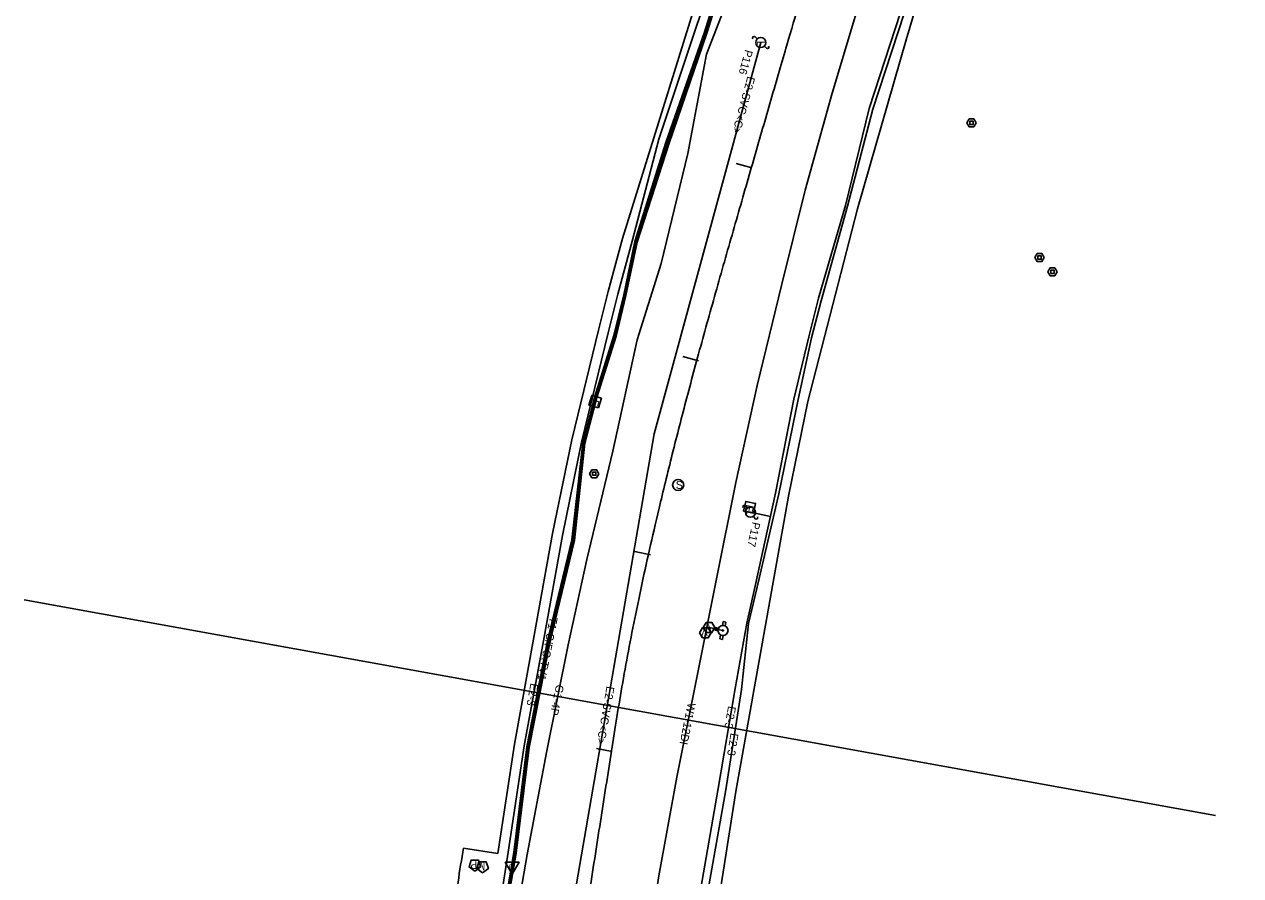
# Model space of a CAD drawing. Extents: x 1991878 to 2008544, y 770238 to 1141211.
# Drawn here: x 2007275 to 2007882, y 1138111 to 1138537 of the extents above; entities that cross this region are included whole.
import ezdxf

# ---------------------------------------------------------------- set-up
doc = ezdxf.new("R2010")
doc.units = 0
for name, color, linetype in [('RD_EX_SU_Elec', 7, 'Continuous'), ('RD_EX_SU_Gas', 7, 'Continuous'), ('RD_EX_SU_H2O', 7, 'Continuous'), ('RD_EX_SU_Misc', 7, 'Continuous'), ('RD_EX_SU_Pole', 7, 'Continuous'), ('RD_EX_SU_Sewer', 7, 'Continuous'), ('RD_EX_SU_SwpLmt', 7, 'Continuous'), ('RD_EX_SU_Telecom', 7, 'Continuous'), ('RD_EX_SU_TX_Elec', 7, 'Continuous'), ('RD_EX_SU_TX_Gas', 7, 'Continuous'), ('RD_EX_SU_TX_H2O', 7, 'Continuous'), ('RD_EX_SU_TX_Pole', 7, 'Continuous'), ('RD_EX_SU_TX_Telecom', 7, 'Continuous'), ('RD_HC_Cl', 7, 'Continuous')]:
    doc.layers.add(name, color=color, linetype=linetype)

msp = doc.modelspace()

# ---------------------------------------------------------------- linework, layer by layer
at = {"layer": 'RD_EX_SU_Elec'}
msp.add_line((2007637.43, 1138292.75), (2007647.39, 1138290.57), dxfattribs=at)
for points in [[(2007706.83, 1138822.62), (2007704.76, 1138818.43), (2007686.36, 1138768.29), (2007670.15, 1138718.93), (2007655.58, 1138671.59), (2007638.85, 1138621.77), (2007624.34, 1138576.36), (2007610.08, 1138534.72), (2007591.61, 1138479.18), (2007578.34, 1138428.3), (2007571.2, 1138401.76), (2007566.3, 1138382.49), (2007552.98, 1138327.8), (2007543.47, 1138281.15), (2007534.02, 1138228.49), (2007524.41, 1138175.98), (2007516.35, 1138122.86), (2007508.64, 1138073.54), (2007501.32, 1138025.38), (2007493.66, 1137973), (2007490.32, 1137950.52), (2007490.01, 1137946.93)], [(2007712.49, 1138542.43), (2007696.83, 1138494.53), (2007685.02, 1138446.06), (2007671.46, 1138399.73), (2007666.58, 1138380.33), (2007659.17, 1138349.31), (2007649.94, 1138302.21), (2007639.62, 1138255.08), (2007635.71, 1138237.27), (2007629.85, 1138204.64), (2007621.3, 1138154.75), (2007612.68, 1138104.93), (2007606.14, 1138053.84), (2007599.77, 1138007.06), (2007596.84, 1137986.3), (2007591.59, 1137955.78), (2007589.06, 1137927.38), (2007586.07, 1137909.2), (2007586.26, 1137894.25), (2007587.74, 1137889.07)], [(2007714.26, 1138542.06), (2007698.61, 1138494.14), (2007686.02, 1138445.77), (2007672.82, 1138398.47), (2007667.98, 1138379.97), (2007661.22, 1138349.15), (2007651.59, 1138301.88), (2007640.57, 1138254.66), (2007636.43, 1138237.15), (2007632.95, 1138204.15), (2007625.16, 1138154.04), (2007616.3, 1138104.21), (2007609.78, 1138053.19), (2007601.94, 1138006.51), (2007599.37, 1137985.94), (2007593.19, 1137955.57), (2007590.35, 1137927.51), (2007587.53, 1137909.08), (2007587.7, 1137893.93), (2007587.74, 1137889.07)], [(2007538.15, 1137074.35), (2007519.64, 1137210), (2007505.46, 1137340.1), (2007504.07, 1137566.44), (2007504, 1137727.5), (2007520.49, 1137915.5), (2007511.47, 1137939.68), (2007504.53, 1137943.1), (2007494.61, 1137946.88), (2007490.01, 1137946.93), (2007494.71, 1137947.7), (2007504.89, 1137945.37), (2007508.98, 1137946.44), (2007510.73, 1137950.05), (2007517.78, 1137999.33), (2007545.65, 1138079.09), (2007589.39, 1138331.96), (2007642.59, 1138527.53)]]:
    msp.add_lwpolyline(points, dxfattribs=at)
msp.add_lwpolyline([(2007638.93, 1138292.25), (2007639.98, 1138297.14), (2007635.09, 1138298.19), (2007634.04, 1138293.3)], close=True, dxfattribs=at)
at = {"layer": 'RD_EX_SU_Gas'}
msp.add_lwpolyline([(2007634.42, 1138570.59), (2007615.51, 1138521.62), (2007606.1, 1138472.02), (2007592.8, 1138417.02), (2007580.86, 1138378.9), (2007568.59, 1138323.23), (2007555.66, 1138269.15), (2007546.41, 1138226.42), (2007535.61, 1138173.44), (2007525.93, 1138121.66), (2007517.31, 1138072.53), (2007510.66, 1138020.37), (2007506.64, 1137971.23), (2007506.3, 1137957.32), (2007504.57, 1137918.34), (2007499.45, 1137870.97), (2007496.13, 1137817.71), (2007491.79, 1137765.75), (2007491.75, 1137759.97), (2007489.77, 1137717.72), (2007489.6, 1137706.9), (2007487.5, 1137663.95)], dxfattribs=at)
at = {"layer": 'RD_EX_SU_H2O'}
for p, q in [((2007623.89, 1138238.11), (2007623.49, 1138236.12)), ((2007625.13, 1138237.87), (2007623.89, 1138238.11)), ((2007624.74, 1138235.92), (2007625.13, 1138237.87)), ((2007619.89, 1138235.08), (2007619.64, 1138233.84)), ((2007619.64, 1138233.84), (2007621.21, 1138233.53)), ((2007621.49, 1138234.76), (2007619.89, 1138235.08)), ((2007622.55, 1138231.39), (2007622.17, 1138229.46)), ((2007622.17, 1138229.46), (2007623.41, 1138229.22)), ((2007623.41, 1138229.22), (2007623.78, 1138231.09))]:
    msp.add_line(p, q, dxfattribs=at)
for points in [[(2007548.97, 1137663.53), (2007550.1, 1137712.27), (2007552.81, 1137762.67), (2007556.77, 1137812.3), (2007561.23, 1137862.39), (2007566.19, 1137911.98), (2007570.32, 1137961.89), (2007576.38, 1138011.99), (2007581, 1138044.96), (2007583.81, 1138061.61), (2007586.91, 1138079.97), (2007591.59, 1138111.01), (2007600.73, 1138160.37), (2007610.7, 1138210.15), (2007620.53, 1138259.51), (2007630.19, 1138307.66), (2007640.83, 1138356.11), (2007652.92, 1138406.01), (2007664.84, 1138453.65), (2007678.31, 1138502.25), (2007692.96, 1138551.24)], [(2007615.71, 1138235.31), (2007616.04, 1138235.25), (2007622.84, 1138233.72), (2007623.73, 1138233.61)]]:
    msp.add_lwpolyline(points, dxfattribs=at)
for points in [[(2007613.88, 1138235.11), (2007615.32, 1138232.61), (2007618.21, 1138232.61), (2007619.65, 1138235.11), (2007618.21, 1138237.61), (2007615.32, 1138237.61)], [(2007612.06, 1138232.54), (2007613.5, 1138230.04), (2007616.39, 1138230.04), (2007617.83, 1138232.54), (2007616.39, 1138235.04), (2007613.5, 1138235.04)], [(2007499.7, 1138113.33), (2007502.6, 1138115.44), (2007501.5, 1138118.85), (2007497.91, 1138118.85), (2007496.8, 1138115.44)], [(2007503.56, 1138112.54), (2007506.46, 1138114.65), (2007505.35, 1138118.06), (2007501.77, 1138118.06), (2007500.66, 1138114.65)]]:
    msp.add_lwpolyline(points, close=True, dxfattribs=at)
for radius in [2.52, 0.315]:
    msp.add_circle((2007623.73, 1138233.61), radius, dxfattribs=at)
for start, end in [(153.00647, 181.97371), (242.09965, 271.07597), (66.44593, 95.42225)]:
    msp.add_arc((2007623.73, 1138233.61), 2.52, start, end, dxfattribs=at)
at = {"layer": 'RD_EX_SU_Misc'}
msp.add_lwpolyline([(2007518.34, 1138111.79), (2007521.81, 1138117.79), (2007514.88, 1138117.79)], close=True, dxfattribs=at)
at = {"layer": 'RD_EX_SU_Pole'}
for p, q in [((2007639.76, 1138530.36), (2007640.83, 1138529.3)), ((2007644.36, 1138525.77), (2007645.42, 1138524.7)), ((2007635.06, 1138295.96), (2007635.95, 1138294.76)), ((2007638.92, 1138290.73), (2007639.81, 1138289.53))]:
    msp.add_line(p, q, dxfattribs=at)
for centre in [(2007642.59, 1138527.53), (2007637.43, 1138292.75)]:
    msp.add_circle(centre, 2.5, dxfattribs=at)
for centre, start, end in [((2007639.23, 1138529.83), 45, 225), ((2007645.95, 1138525.23), 225, 45), ((2007634.45, 1138295.52), 36.44594, 216.44594), ((2007640.41, 1138289.97), 216.44594, 36.44594)]:
    msp.add_arc(centre, 0.75, start, end, dxfattribs=at)
at = {"layer": 'RD_EX_SU_Sewer'}
for points in [[(2007750.24, 1138487.35), (2007749.09, 1138489.35), (2007746.78, 1138489.35), (2007745.62, 1138487.35), (2007746.78, 1138485.35), (2007749.09, 1138485.35)], [(2007748.75, 1138488.17), (2007747.12, 1138488.17), (2007747.11, 1138486.53), (2007748.75, 1138486.53)], [(2007784.25, 1138420.03), (2007783.09, 1138422.03), (2007780.79, 1138422.03), (2007779.63, 1138420.03), (2007780.79, 1138418.03), (2007783.09, 1138418.03)], [(2007782.76, 1138420.84), (2007781.12, 1138420.84), (2007781.12, 1138419.21), (2007782.75, 1138419.21)], [(2007790.71, 1138412.91), (2007789.56, 1138414.9), (2007787.25, 1138414.9), (2007786.09, 1138412.91), (2007787.25, 1138410.91), (2007789.56, 1138410.91)], [(2007789.22, 1138413.72), (2007787.59, 1138413.72), (2007787.58, 1138412.09), (2007789.22, 1138412.09)], [(2007561.68, 1138312.01), (2007560.53, 1138314), (2007558.22, 1138314), (2007557.07, 1138312.01), (2007558.22, 1138310.01), (2007560.53, 1138310.01)], [(2007560.19, 1138312.82), (2007558.56, 1138312.82), (2007558.56, 1138311.19), (2007560.19, 1138311.19)]]:
    msp.add_lwpolyline(points, close=True, dxfattribs=at)
msp.add_circle((2007601.32, 1138306.39), 2.75, dxfattribs=at)
at = {"layer": 'RD_EX_SU_SwpLmt'}
msp.add_line((2007493.97, 1138124.93), (2007511.19, 1138122.18), dxfattribs=at)
for points in [[(2007702.34, 1138824.83), (2007634.1, 1138623.32), (2007619.59, 1138577.94), (2007573.51, 1138429.58), (2007566.36, 1138403.03), (2007561.45, 1138383.7), (2007548.1, 1138328.89), (2007538.56, 1138282.1), (2007529.1, 1138229.38), (2007519.48, 1138176.81), (2007511.19, 1138122.18)], [(2007715.28, 1138528.93), (2007690.88, 1138444.46), (2007666.14, 1138348.11), (2007656.52, 1138300.81), (2007630.12, 1138153.21), (2007606.92, 1138005.78), (2007592.75, 1137889.42)]]:
    msp.add_lwpolyline(points, dxfattribs=at)
for centre, radius, start, end in [((2009858.48, 1137910.13), 2230.75, 135.28907, 163.89519), ((2011139.83, 1137542.45), 3692.1, 170.92287, 171.45757)]:
    msp.add_arc(centre, radius, start, end, dxfattribs=at)
at = {"layer": 'RD_EX_SU_Telecom'}
for points in [[(2007628.19, 1138574.88), (2007615.18, 1138532.43), (2007595.94, 1138477.43), (2007580.19, 1138427.98), (2007574.61, 1138401.28), (2007569.71, 1138380.96), (2007560.17, 1138350.06), (2007554.14, 1138327.34), (2007548.86, 1138278.86), (2007536.67, 1138228.27), (2007526.24, 1138175.25), (2007519.69, 1138122.42), (2007511.37, 1138073.33), (2007502.97, 1138025.15), (2007497.48, 1137973.05), (2007494.94, 1137951.7), (2007491.53, 1137942.52), (2007485.03, 1137942.28)], [(2007627.59, 1138575.05), (2007614.5, 1138532.66), (2007595.23, 1138477.59), (2007579.66, 1138428.05), (2007574.13, 1138401.36), (2007569.16, 1138381.1), (2007559.54, 1138350.07), (2007553.63, 1138327.41), (2007548.17, 1138278.88), (2007536.03, 1138228.39), (2007525.7, 1138175.56), (2007519.11, 1138122.6), (2007510.79, 1138073.46), (2007502.45, 1138025.25), (2007496.97, 1137973.16), (2007494.45, 1137951.63), (2007491.1, 1137942.88), (2007488.59, 1137941.59)], [(2007628.91, 1138574.72), (2007615.65, 1138532.16), (2007596.75, 1138477.17), (2007580.91, 1138427.76), (2007575.16, 1138401.11), (2007570.39, 1138380.76), (2007560.7, 1138350.03), (2007554.69, 1138327.28), (2007549.53, 1138278.6), (2007537.28, 1138228.23), (2007526.8, 1138175.21), (2007520.39, 1138122.41), (2007511.93, 1138073.21), (2007503.52, 1138024.98), (2007498.02, 1137972.97), (2007495.54, 1137951.65), (2007491.98, 1137941.97), (2007488.59, 1137941.59)]]:
    msp.add_lwpolyline(points, dxfattribs=at)
msp.add_lwpolyline([(2007561.54, 1138344.95), (2007562.93, 1138349.75), (2007558.12, 1138351.14), (2007556.74, 1138346.34)], close=True, dxfattribs=at)
at = {"layer": 'RD_HC_Cl'}
for p, q in [((2007630.37, 1138467.05), (2007638.06, 1138464.86)), ((2007603.68, 1138370.52), (2007611.41, 1138368.47)), ((2007579.7, 1138273.11), (2007587.51, 1138271.38)), ((2007274.54, 1138248.89), (2007869.86, 1138141.15)), ((2007560.49, 1138174.58), (2007568.38, 1138173.24))]:
    msp.add_line(p, q, dxfattribs=at)
msp.add_open_spline([(2008468.44, 1139784.65), (2008330.54, 1139636.27), (2008112.04, 1139402.61), (2008010.65, 1139269.99), (2007954.96, 1139181.47), (2007845.36, 1139006.33), (2007807.05, 1138915.36), (2007714.1, 1138721), (2007657.93, 1138535.69), (2007584.82, 1138278.81), (2007557.24, 1138105.93), (2007524.47, 1137887.62), (2007511.86, 1137606.6), (2007518.19, 1137380.97), (2007535.52, 1137158.14), (2007573, 1136960.76), (2007648.83, 1136694.4), (2007817.41, 1136298.79), (2008044.24, 1135795.68), (2008373.08, 1135014.28)], degree=2, dxfattribs=at)

# ---------------------------------------------------------------- texts
at = {"layer": 'RD_EX_SU_Elec'}
for s, rotation, p in [('E2-SVC<C>', 254.78251, (2007635.98, 1138510.85)), ('E', 257.9388, (2007635.31, 1138296.82))]:
    msp.add_text(s, height=4, rotation=rotation, dxfattribs=at).set_placement(p)
at = {"layer": 'RD_EX_SU_H2O'}
for s, p in [('V', (2007616.15, 1138234.42)), ('V', (2007617.97, 1138236.99)), ('P', (2007500.86, 1138118.26)), ('M', (2007504.93, 1138117.58))]:
    msp.add_text(s, height=3.75, rotation=180, dxfattribs=at).set_placement(p)
at = {"layer": 'RD_EX_SU_Misc'}
msp.add_text('U', height=2.4, rotation=180, dxfattribs=at).set_placement((2007519.1, 1138116.99))
at = {"layer": 'RD_EX_SU_Pole'}
for rotation, p in [(270, (2007640.66, 1138528.34)), (261.44594, (2007635.64, 1138293.83))]:
    msp.add_text('L', height=4, rotation=rotation, dxfattribs=at).set_placement(p)
at = {"layer": 'RD_EX_SU_Sewer'}
msp.add_text('S', height=3.93, dxfattribs=at).set_placement((2007600.12, 1138304.43))
at = {"layer": 'RD_EX_SU_Telecom'}
msp.add_text('F', height=4, rotation=253.89576, dxfattribs=at).set_placement((2007558.22, 1138349.69))
at = {"layer": 'RD_EX_SU_TX_Elec'}
for s, rotation, p in [('E2-3', 259.63701, (2007527.56, 1138207.5)), ('E2-SVC<C>', 260.18581, (2007565.57, 1138205.99)), ('E2-3', 260.27881, (2007626.32, 1138196.08)), ('E2-3', 261.15332, (2007627.53, 1138182.55))]:
    msp.add_text(s, height=4, rotation=rotation, dxfattribs=at).set_placement(p)
at = {"layer": 'RD_EX_SU_TX_Gas'}
msp.add_text('G1-4P', height=4, rotation=258.48637, dxfattribs=at).set_placement((2007540.37, 1138206.81))
at = {"layer": 'RD_EX_SU_TX_H2O'}
msp.add_text('W1-12DI', height=4, rotation=258.67427, dxfattribs=at).set_placement((2007606.16, 1138197.69))
at = {"layer": 'RD_EX_SU_TX_Pole'}
for s, rotation, p in [('P116', 254.52888, (2007634.85, 1138524.18)), ('P117', 257.56159, (2007638.51, 1138288.11))]:
    msp.add_text(s, height=4, rotation=rotation, dxfattribs=at).set_placement(p)
at = {"layer": 'RD_EX_SU_TX_Telecom'}
msp.add_text('T1-C/FO,TV1', height=4, rotation=258.8196, dxfattribs=at).set_placement((2007537.23, 1138240.65))

doc.saveas('drawing.dxf')
